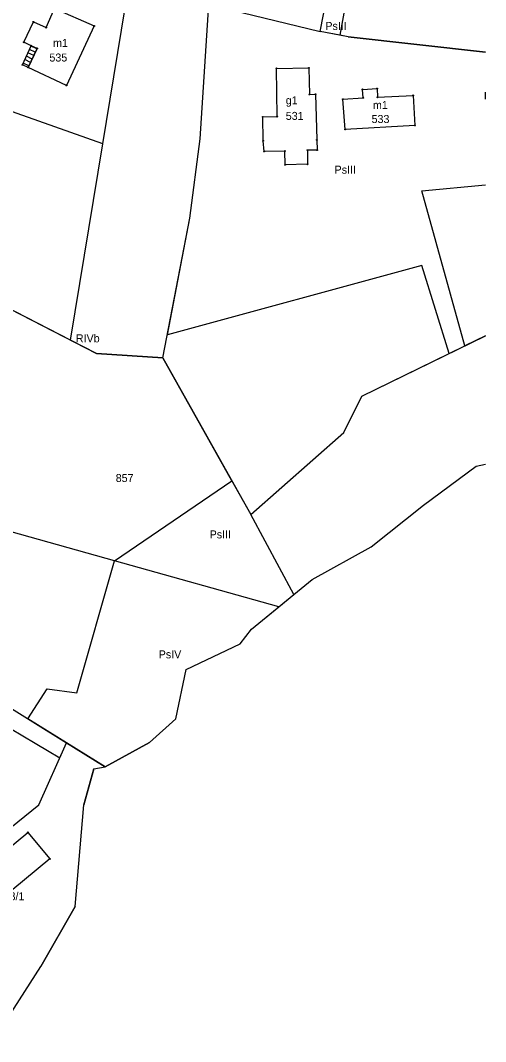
# Model space of a CAD drawing. Extents: x 7498273 to 7499989, y 5499795 to 5500810.
# Drawn here: x 7499901.7 to 7499988.9, y 5500031.7 to 5500223.1 of the extents above; entities that cross this region are included whole.
import ezdxf

# ---------------------------------------------------------------- set-up
doc = ezdxf.new("R2010")
doc.units = 0
for name, color, linetype in [('209-oznaczenie konturu klasyfikacyjnego', 7, 'Continuous'), ('211-numer działki ewidencyjnej', 7, 'Continuous'), ('217-kontur klasyfikacyjny', 7, 'Continuous'), ('218-kontur użytku gruntowego', 7, 'Continuous'), ('219-działka ewidencyjna', 7, 'Continuous'), ('312-budynek ewidencyjny', 7, 'Continuous'), ('312-oznaczenie budynku ewidencyjnego', 7, 'Continuous'), ('312-oznaczenie budynku ewidencyjnego-Atr117', 7, 'Continuous'), ('352-schody', 7, 'Continuous'), ('Punkt budynku', 7, 'Continuous')]:
    doc.layers.add(name, color=color, linetype=linetype)

# ---------------------------------------------------------------- blocks, each defined once
blk = doc.blocks.new('PUNKTBUD')
blk.add_circle((0, 0), 0.09)

msp = doc.modelspace()

# ---------------------------------------------------------------- linework, layer by layer
at = {"layer": '217-kontur klasyfikacyjny'}
for points in [[(7499975.23, 5500295.42), (7499961.52, 5500220.29)], [(7499957.84, 5500220.99), (7499963.65, 5500250.66)], [(7499917.09, 5500199.97), (7499921.96, 5500229.68)], [(7499935.38, 5500200.87), (7499936.97, 5500226.04)], [(7499936.97, 5500226.04), (7499957.84, 5500220.99)], [(7499961.52, 5500220.29), (7499957.84, 5500220.99)], [(7499963.12, 5500219.99), (7499961.52, 5500220.29)], [(7499988.876, 5500217.143), (7499963.12, 5500219.99)], [(7499917.09, 5500199.97), (7499889, 5500209.85)], [(7499988.86, 5500208.55), (7499988.876, 5500209.61)], [(7499988.876, 5500208.551), (7499988.86, 5500208.55)], [(7499988.876, 5500208.297), (7499988.86, 5500208.55)], [(7499911.06, 5500163.14), (7499917.09, 5500199.97)], [(7499933.45, 5500186.04), (7499935.38, 5500200.87)], [(7499976.95, 5500191.15), (7499988.876, 5500192.238)], [(7499984.98, 5500162.07), (7499976.95, 5500191.15)], [(7499911.06, 5500163.14), (7499859.7, 5500189.56)], [(7499929.22, 5500164.15), (7499933.45, 5500186.04)], [(7499976.93, 5500177.14), (7499929.22, 5500164.15)], [(7499982.07, 5500160.65), (7499976.93, 5500177.14)], [(7499988.876, 5500163.975), (7499984.98, 5500162.07)], [(7499915.93, 5500160.63), (7499911.06, 5500163.14)], [(7499982.07, 5500160.65), (7499984.98, 5500162.07)], [(7499928.39, 5500159.82), (7499915.93, 5500160.63)], [(7499941.3, 5500136.82), (7499928.39, 5500159.82)], [(7499965.69, 5500152.63), (7499982.07, 5500160.65)], [(7499962.28, 5500145.82), (7499965.69, 5500152.63)], [(7499944.85, 5500130.5), (7499962.28, 5500145.82)], [(7499919.32, 5500121.81), (7499844.87, 5500142.67)], [(7499977.21, 5500132.26), (7499987.12, 5500139.56)], [(7499987.12, 5500139.56), (7499988.876, 5500139.934)], [(7499919.32, 5500121.81), (7499941.3, 5500136.82)], [(7499941.3, 5500136.82), (7499944.85, 5500130.5)], [(7499967.42, 5500124.41), (7499977.21, 5500132.26)], [(7499952.95, 5500115.49), (7499944.85, 5500130.5)], [(7499956.38, 5500118.3), (7499967.42, 5500124.41)], [(7499912.22, 5500097.03), (7499919.32, 5500121.81)], [(7499950.1, 5500113.17), (7499919.32, 5500121.81)], [(7499952.95, 5500115.49), (7499956.38, 5500118.3)], [(7499950.1, 5500113.17), (7499952.95, 5500115.49)], [(7499945.01, 5500109), (7499950.1, 5500113.17)], [(7499942.89, 5500106.25), (7499945.01, 5500109)], [(7499932.77, 5500101.43), (7499942.89, 5500106.25)], [(7499874.29, 5500105.47), (7499909.06, 5500084.87)], [(7499930.81, 5500092.17), (7499932.77, 5500101.43)], [(7499903.08, 5500092.18), (7499906.7, 5500097.78)], [(7499906.7, 5500097.78), (7499912.22, 5500097.03)], [(7499910.31, 5500087.68), (7499903.08, 5500092.18)], [(7499925.86, 5500087.76), (7499930.81, 5500092.17)], [(7499909.06, 5500084.87), (7499910.31, 5500087.68)], [(7499910.31, 5500087.68), (7499917.57, 5500083.22)], [(7499917.57, 5500083.22), (7499925.86, 5500087.76)]]:
    msp.add_lwpolyline(points, dxfattribs=at)
at = {"layer": '218-kontur użytku gruntowego'}
for points in [[(7499975.23, 5500295.42), (7499961.52, 5500220.29)], [(7499957.84, 5500220.99), (7499963.65, 5500250.66)], [(7499917.09, 5500199.97), (7499921.96, 5500229.68)], [(7499935.38, 5500200.87), (7499936.97, 5500226.04)], [(7499936.97, 5500226.04), (7499957.84, 5500220.99)], [(7499961.52, 5500220.29), (7499957.84, 5500220.99)], [(7499963.12, 5500219.99), (7499961.52, 5500220.29)], [(7499988.876, 5500217.143), (7499963.12, 5500219.99)], [(7499917.09, 5500199.97), (7499889, 5500209.85)], [(7499988.86, 5500208.55), (7499988.876, 5500209.61)], [(7499988.876, 5500208.551), (7499988.86, 5500208.55)], [(7499988.876, 5500208.297), (7499988.86, 5500208.55)], [(7499911.06, 5500163.14), (7499917.09, 5500199.97)], [(7499933.45, 5500186.04), (7499935.38, 5500200.87)], [(7499976.95, 5500191.15), (7499988.876, 5500192.238)], [(7499984.98, 5500162.07), (7499976.95, 5500191.15)], [(7499911.06, 5500163.14), (7499859.7, 5500189.56)], [(7499929.22, 5500164.15), (7499933.45, 5500186.04)], [(7499976.93, 5500177.14), (7499929.22, 5500164.15)], [(7499982.07, 5500160.65), (7499976.93, 5500177.14)], [(7499988.876, 5500163.975), (7499984.98, 5500162.07)], [(7499915.93, 5500160.63), (7499911.06, 5500163.14)], [(7499982.07, 5500160.65), (7499984.98, 5500162.07)], [(7499928.39, 5500159.82), (7499915.93, 5500160.63)], [(7499941.3, 5500136.82), (7499928.39, 5500159.82)], [(7499965.69, 5500152.63), (7499982.07, 5500160.65)], [(7499962.28, 5500145.82), (7499965.69, 5500152.63)], [(7499944.85, 5500130.5), (7499962.28, 5500145.82)], [(7499919.32, 5500121.81), (7499844.87, 5500142.67)], [(7499977.21, 5500132.26), (7499987.12, 5500139.56)], [(7499987.12, 5500139.56), (7499988.876, 5500139.934)], [(7499919.32, 5500121.81), (7499941.3, 5500136.82)], [(7499941.3, 5500136.82), (7499944.85, 5500130.5)], [(7499967.42, 5500124.41), (7499977.21, 5500132.26)], [(7499952.95, 5500115.49), (7499944.85, 5500130.5)], [(7499956.38, 5500118.3), (7499967.42, 5500124.41)], [(7499912.22, 5500097.03), (7499919.32, 5500121.81)], [(7499950.1, 5500113.17), (7499919.32, 5500121.81)], [(7499952.95, 5500115.49), (7499956.38, 5500118.3)], [(7499950.1, 5500113.17), (7499952.95, 5500115.49)], [(7499945.01, 5500109), (7499950.1, 5500113.17)], [(7499942.89, 5500106.25), (7499945.01, 5500109)], [(7499932.77, 5500101.43), (7499942.89, 5500106.25)], [(7499874.29, 5500105.47), (7499909.06, 5500084.87)], [(7499930.81, 5500092.17), (7499932.77, 5500101.43)], [(7499903.08, 5500092.18), (7499906.7, 5500097.78)], [(7499906.7, 5500097.78), (7499912.22, 5500097.03)], [(7499910.31, 5500087.68), (7499903.08, 5500092.18)], [(7499925.86, 5500087.76), (7499930.81, 5500092.17)], [(7499909.06, 5500084.87), (7499910.31, 5500087.68)], [(7499917.57, 5500083.22), (7499910.31, 5500087.68)], [(7499917.57, 5500083.22), (7499925.86, 5500087.76)], [(7499915.44, 5500082.83), (7499917.57, 5500083.22)], [(7499913.53, 5500076.05), (7499915.44, 5500082.83)], [(7499911.95, 5500056.99), (7499913.53, 5500076.05)], [(7499905.5, 5500045.76), (7499911.95, 5500056.99)], [(7499896.42, 5500031.7), (7499905.5, 5500045.76)]]:
    msp.add_lwpolyline(points, dxfattribs=at)
at = {"layer": '219-działka ewidencyjna'}
for points in [[(7499957.84, 5500220.99), (7499963.65, 5500250.66)], [(7499935.38, 5500200.87), (7499936.97, 5500226.04)], [(7499936.97, 5500226.04), (7499957.84, 5500220.99)], [(7499963.12, 5500219.99), (7499957.84, 5500220.99)], [(7499963.12, 5500219.99), (7499988.876, 5500217.143)], [(7499933.45, 5500186.04), (7499935.38, 5500200.87)], [(7499853.17, 5500192.92), (7499915.93, 5500160.63)], [(7499928.39, 5500159.82), (7499933.45, 5500186.04)], [(7499965.69, 5500152.63), (7499988.876, 5500163.974)], [(7499915.93, 5500160.63), (7499928.39, 5500159.82)], [(7499928.39, 5500159.82), (7499944.85, 5500130.5)], [(7499962.28, 5500145.82), (7499965.69, 5500152.63)], [(7499944.85, 5500130.5), (7499962.28, 5500145.82)], [(7499977.21, 5500132.26), (7499987.12, 5500139.56)], [(7499987.12, 5500139.56), (7499988.876, 5500139.934)], [(7499967.42, 5500124.41), (7499977.21, 5500132.26)], [(7499842.63, 5500129.86), (7499910.31, 5500087.68)], [(7499956.38, 5500118.3), (7499967.42, 5500124.41)], [(7499945.01, 5500109), (7499956.38, 5500118.3)], [(7499942.89, 5500106.25), (7499945.01, 5500109)], [(7499932.77, 5500101.43), (7499942.89, 5500106.25)], [(7499930.81, 5500092.17), (7499932.77, 5500101.43)], [(7499925.86, 5500087.76), (7499930.81, 5500092.17)], [(7499905.13, 5500076.06), (7499910.31, 5500087.68)], [(7499917.57, 5500083.22), (7499910.31, 5500087.68)], [(7499925.86, 5500087.76), (7499917.57, 5500083.22)], [(7499915.44, 5500082.83), (7499917.57, 5500083.22)], [(7499915.44, 5500082.83), (7499913.53, 5500076.05)], [(7499893.55, 5500066.75), (7499905.13, 5500076.06)], [(7499911.95, 5500056.99), (7499913.53, 5500076.05)], [(7499911.95, 5500056.99), (7499905.5, 5500045.76)], [(7499896.42, 5500031.7), (7499905.5, 5500045.76)]]:
    msp.add_lwpolyline(points, dxfattribs=at)
at = {"layer": '312-budynek ewidencyjny'}
for points in [[(7499906.47, 5500221.73), (7499908.06, 5500225.32)], [(7499908.06, 5500225.32), (7499915.49, 5500222.03)], [(7499902.32, 5500218.98), (7499904.1, 5500222.78)], [(7499904.1, 5500222.78), (7499906.47, 5500221.73)], [(7499915.49, 5500222.03), (7499910.28, 5500210.9)], [(7499903.7, 5500218.33), (7499902.32, 5500218.98)], [(7499903.12, 5500214.26), (7499904.79, 5500217.82)], [(7499904.79, 5500217.82), (7499903.7, 5500218.33)], [(7499910.28, 5500210.9), (7499903.12, 5500214.26)], [(7499949.67, 5500214.07), (7499955.76, 5500214.17)], [(7499949.81, 5500205.05), (7499949.67, 5500214.07)], [(7499955.76, 5500214.17), (7499955.84, 5500209.22)], [(7499965.82, 5500210.15), (7499968.54, 5500210.29)], [(7499965.94, 5500208.58), (7499965.82, 5500210.15)], [(7499968.54, 5500210.29), (7499968.62, 5500208.68)], [(7499955.84, 5500209.22), (7499956.99, 5500209.23)], [(7499956.99, 5500209.23), (7499957.25, 5500200.67)], [(7499962.12, 5500208.29), (7499965.94, 5500208.58)], [(7499962.55, 5500202.64), (7499962.12, 5500208.29)], [(7499968.62, 5500208.68), (7499975.27, 5500209.03)], [(7499975.27, 5500209.03), (7499975.64, 5500203.39)], [(7499947.11, 5500205.01), (7499949.81, 5500205.05)], [(7499947.17, 5500200.52), (7499947.11, 5500205.01)], [(7499975.64, 5500203.39), (7499962.55, 5500202.64)], [(7499947.35, 5500198.52), (7499947.17, 5500200.52)], [(7499957.25, 5500200.67), (7499957.28, 5500198.77)], [(7499951.23, 5500198.6), (7499947.35, 5500198.52)], [(7499951.28, 5500196.03), (7499951.23, 5500198.6)], [(7499957.28, 5500198.77), (7499955.46, 5500198.74)], [(7499955.46, 5500198.74), (7499955.5, 5500196.12)], [(7499955.5, 5500196.12), (7499951.28, 5500196.03)], [(7499893.51, 5500063.02), (7499903.08, 5500070.89)], [(7499903.08, 5500070.89), (7499907.16, 5500065.94)], [(7499907.16, 5500065.94), (7499897.59, 5500058.07)]]:
    msp.add_lwpolyline(points, dxfattribs=at)
at = {"layer": '352-schody'}
msp.add_lwpolyline([(7499902.03, 5500214.77), (7499903.7, 5500218.33), (7499904.79, 5500217.82), (7499903.12, 5500214.26)], close=True, dxfattribs=at)
msp.add_lwpolyline([(7499902.03, 5500214.77), (7499903.7, 5500218.33), (7499904.79, 5500217.82), (7499903.12, 5500214.26)], close=True, dxfattribs=at)
for points in [[(7499904.457, 5500217.111), (7499903.368, 5500217.622)], [(7499904.755, 5500217.744), (7499903.665, 5500218.256)], [(7499903.565, 5500215.21), (7499902.476, 5500215.721)], [(7499903.863, 5500215.843), (7499902.773, 5500216.354)], [(7499904.16, 5500216.477), (7499903.071, 5500216.988)], [(7499903.268, 5500214.576), (7499902.179, 5500215.087)]]:
    msp.add_lwpolyline(points, dxfattribs=at)

# ---------------------------------------------------------------- block references
at = {"layer": 'Punkt budynku'}
for p in [(7499904.1, 5500222.78), (7499906.47, 5500221.73), (7499915.49, 5500222.03), (7499902.32, 5500218.98), (7499903.7, 5500218.33), (7499904.79, 5500217.82), (7499902.03, 5500214.77), (7499903.12, 5500214.26), (7499949.67, 5500214.07), (7499955.76, 5500214.17), (7499910.28, 5500210.9), (7499965.82, 5500210.15), (7499968.54, 5500210.29), (7499955.84, 5500209.22), (7499956.99, 5500209.23), (7499962.12, 5500208.29), (7499965.94, 5500208.58), (7499968.62, 5500208.68), (7499975.27, 5500209.03), (7499947.11, 5500205.01), (7499949.81, 5500205.05), (7499962.55, 5500202.64), (7499975.64, 5500203.39), (7499947.17, 5500200.52), (7499957.25, 5500200.67), (7499947.35, 5500198.52), (7499951.23, 5500198.6), (7499955.46, 5500198.74), (7499957.28, 5500198.77), (7499951.28, 5500196.03), (7499955.5, 5500196.12), (7499903.08, 5500070.89), (7499907.16, 5500065.94)]:
    msp.add_blockref('PUNKTBUD', p, dxfattribs=at)

# ---------------------------------------------------------------- texts
at = {"layer": '209-oznaczenie konturu klasyfikacyjnego'}
for s, p in [('PsIII', (7499958.84, 5500221.29)), ('PsIII', (7499960.56, 5500194.35)), ('RIVb', (7499912.06, 5500162.75)), ('PsIII', (7499937.14, 5500126)), ('PsIV', (7499927.59, 5500103.52))]:
    msp.add_text(s, height=1.5, dxfattribs=at).set_placement(p)
at = {"layer": '211-numer działki ewidencyjnej'}
for s, p in [('857', (7499919.53, 5500136.57)), ('858/1', (7499897.39, 5500058.19))]:
    msp.add_text(s, height=1.5, dxfattribs=at).set_placement(p)
at = {"layer": '312-oznaczenie budynku ewidencyjnego'}
for s, p in [('535', (7499907.1, 5500215.37)), ('531', (7499951.41, 5500204.43)), ('533', (7499967.5, 5500203.85))]:
    msp.add_text(s, height=1.5, dxfattribs=at).set_placement(p)
at = {"layer": '312-oznaczenie budynku ewidencyjnego-Atr117'}
for s, p in [('m1', (7499907.785, 5500218.11)), ('g1', (7499951.409, 5500207.35)), ('m1', (7499967.755, 5500206.47))]:
    msp.add_text(s, height=1.5, dxfattribs=at).set_placement(p)

doc.saveas('drawing.dxf')
